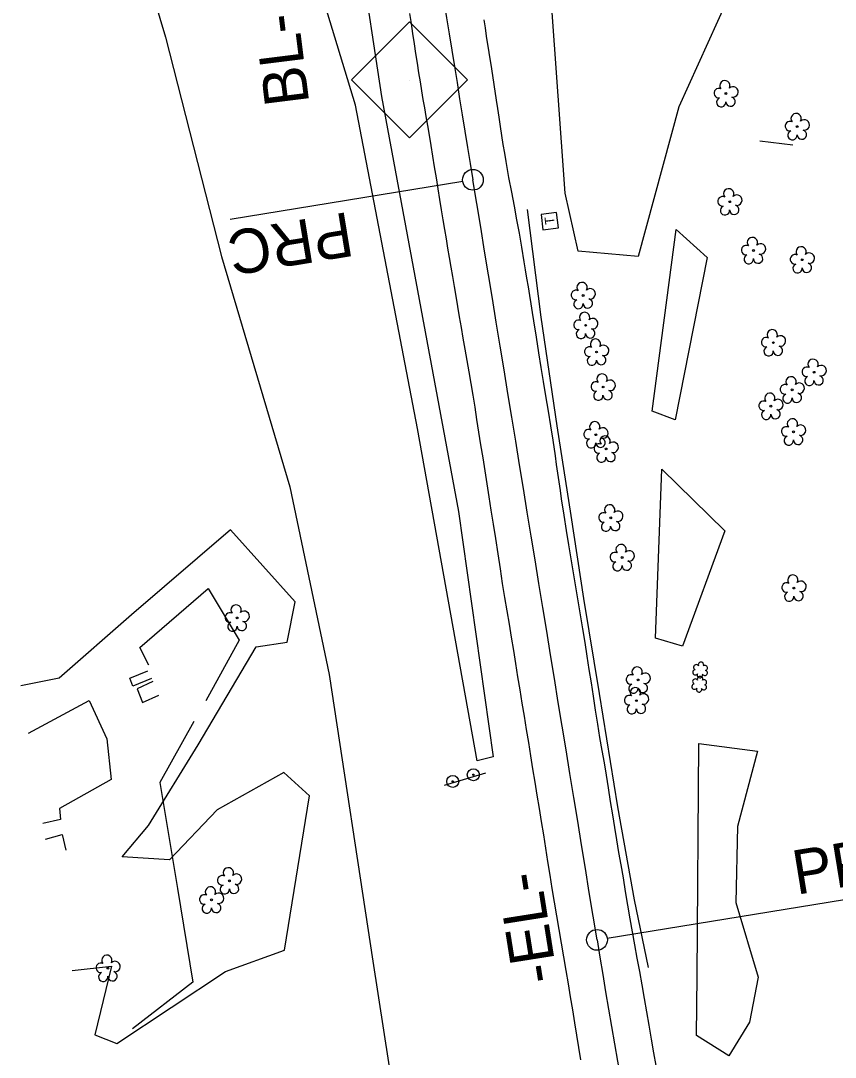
# Model space of a CAD drawing. Extents: x 477009 to 479892, y 492858 to 496862.
# Drawn here: x 478207.5 to 478502.1, y 495186.3 to 495561.1 of the extents above; entities that cross this region are included whole.
import ezdxf

# ---------------------------------------------------------------- set-up
doc = ezdxf.new("R2010")
doc.units = 0
for name, color, linetype in [('CTL Secondary Horizontal and Vertical CELL', 7, 'Continuous'), ('CTL Secondary Horizontal and Vertical Text', 7, 'Continuous'), ('Exist Guardrail', 7, 'Continuous'), ('Exist Horizontal Alignment', 7, 'Continuous'), ('Exist Horizontal Alignment Direction Label', 7, 'Continuous'), ('Exist Other Culture Area Outline', 7, 'Continuous'), ('Exist Other Culture Fence Line', 7, 'Continuous'), ('Exist Other Culture Sign', 7, 'Continuous'), ('Exist Other Culture Sign Post CELL', 7, 'Continuous'), ('Exist Roads EOP', 7, 'Continuous'), ('Exist Roads Soil', 7, 'Continuous'), ('Exist Structure Minor Footbridge', 7, 'Continuous'), ('Exist Utilities Telephone Pedestal CELL', 7, 'Continuous'), ('Exist Vegetation Shrub CELL', 7, 'Continuous'), ('Exist Vegetation Tree CELL', 7, 'Continuous'), ('Exist Vegetation Woods Line', 7, 'Continuous')]:
    doc.layers.add(name, color=color, linetype=linetype)

msp = doc.modelspace()

# ---------------------------------------------------------------- linework, layer by layer
at = {"layer": 'CTL Secondary Horizontal and Vertical CELL'}
msp.add_line((478348.02, 495539.64), (478348.02, 495539.64), dxfattribs=at)
msp.add_lwpolyline([(478327.16, 495539.71), (478348.13, 495560.67), (478369.13, 495539.67), (478348.16, 495518.71)], close=True, dxfattribs=at)
at = {"layer": 'Exist Guardrail'}
msp.add_lwpolyline([(478390.72, 495492.81), (478395.61, 495453.92), (478401.39, 495414.56), (478406.41, 495382.15), (478411, 495352.2), (478416.72, 495317.79), (478423.3, 495276.84), (478429.41, 495243.13), (478434.41, 495218.68)], dxfattribs=at)
at = {"layer": 'Exist Horizontal Alignment'}
for p, q in [((478367.35, 495502.96), (478283.24, 495489.18)), ((478419.63, 495229.31), (478538.1, 495248.58))]:
    msp.add_line(p, q, dxfattribs=at)
for centre in [(478371.05, 495503.57), (478415.93, 495228.7)]:
    msp.add_circle(centre, 3.75, dxfattribs=at)
for centre, radius, start, end in [((501490.44, 499291.54), 23427.66, 188.840055, 189.304896), ((233727.31, 455420.15), 247905.71, 9.2405286, 9.3048963), ((482394.4, 495875.96), 4030.78, 189.24053, 192.1328)]:
    msp.add_arc(centre, radius, start, end, dxfattribs=at)
at = {"layer": 'Exist Other Culture Area Outline'}
for points in [[(478254.78, 495323.26), (478248.04, 495320.44), (478246.94, 495323.36), (478253.52, 495326.05)], [(478255.3, 495322.09), (478249.61, 495319.47), (478251.55, 495314.53), (478257.5, 495317.21)], [(478216.47, 495265.13), (478222.49, 495266.77), (478223.8, 495261.18)]]:
    msp.add_lwpolyline(points, dxfattribs=at)
at = {"layer": 'Exist Other Culture Fence Line'}
for points in [[(478253.89, 495327.99), (478250.6, 495334.44), (478275.37, 495355.8), (478286.52, 495337.09), (478274.45, 495315.11)], [(478270.07, 495307.7), (478257.89, 495285.57), (478264.17, 495247.34), (478269.8, 495213.45), (478247.95, 495196.55)]]:
    msp.add_lwpolyline(points, dxfattribs=at)
at = {"layer": 'Exist Other Culture Sign'}
msp.add_line((478375.65, 495289.05), (478360.61, 495284.48), dxfattribs=at)
at = {"layer": 'Exist Other Culture Sign Post CELL'}
for centre, radius in [((478371.21, 495288.41), 2.18), ((478363.75, 495286), 2.18), ((478363.75, 495286), 0.24), ((478371.21, 495288.41), 0.24)]:
    msp.add_circle(centre, radius, dxfattribs=at)
at = {"layer": 'Exist Roads EOP'}
for points in [[(478410.13, 495185.29), (478409.39, 495189.74), (478408.66, 495194.22), (478407.92, 495198.76), (478407.17, 495203.37), (478406.38, 495208.07), (478405.58, 495212.84), (478404.76, 495217.68), (478403.93, 495222.55), (478403.09, 495227.46), (478402.24, 495232.41), (478401.39, 495237.36), (478400.56, 495242.31), (478399.76, 495247.23), (478398.98, 495252.14), (478398.2, 495257.03), (478397.43, 495261.88), (478396.65, 495266.7), (478395.87, 495271.49), (478395.09, 495276.26), (478394.31, 495281.03), (478393.54, 495285.79), (478392.77, 495290.55), (478392, 495295.31), (478391.23, 495300.07), (478390.45, 495304.83), (478389.66, 495309.59), (478388.87, 495314.36), (478388.09, 495319.12), (478387.32, 495323.88), (478386.56, 495328.63), (478385.79, 495333.39), (478385.02, 495338.15), (478384.23, 495342.91), (478383.43, 495347.68), (478382.62, 495352.55), (478381.8, 495357.62), (478380.97, 495362.88), (478380.14, 495368.34), (478379.31, 495373.8), (478378.5, 495379.04), (478377.71, 495384.08), (478376.94, 495388.9), (478376.19, 495393.61), (478375.44, 495398.32), (478374.7, 495403.02), (478373.97, 495407.71), (478373.25, 495412.35), (478372.53, 495416.88), (478371.82, 495421.32), (478371.12, 495425.66), (478370.41, 495429.91), (478369.7, 495434.1), (478368.99, 495438.22), (478368.28, 495442.28), (478367.57, 495446.27), (478366.89, 495450.18), (478366.22, 495454.01), (478365.58, 495457.76), (478364.96, 495461.44), (478364.35, 495465.04), (478363.75, 495468.57), (478363.16, 495472.01), (478362.59, 495475.42), (478362.01, 495478.82), (478361.45, 495482.22), (478360.89, 495485.6), (478360.32, 495489.06), (478359.73, 495492.67), (478359.12, 495496.42), (478358.48, 495500.33), (478357.83, 495504.29), (478357.19, 495508.21), (478356.55, 495512.1), (478355.92, 495515.95), (478355.3, 495519.68), (478354.72, 495523.19), (478354.16, 495526.49), (478353.63, 495529.57), (478353.12, 495532.59), (478352.6, 495535.72), (478352.08, 495538.95), (478351.55, 495542.29), (478351.01, 495545.72), (478350.46, 495549.22), (478349.91, 495552.8), (478349.36, 495556.44), (478348.79, 495560.12), (478348.22, 495563.76)], [(478374.95, 495561.47), (478375.43, 495558.51), (478375.9, 495555.53), (478376.83, 495549.61), (478377.73, 495543.76), (478378.62, 495538.04), (478379.51, 495532.37), (478379.97, 495529.37), (478380.44, 495526.21), (478380.93, 495522.9), (478381.43, 495519.57), (478381.93, 495516.35), (478382.43, 495513.22), (478382.94, 495510.2), (478383.94, 495504.46), (478384.95, 495499.1), (478385.93, 495494.02), (478386.85, 495489.12), (478387.74, 495484.25), (478388.61, 495479.25), (478389.52, 495473.91), (478389.99, 495471.02), (478390.49, 495467.98), (478390.99, 495464.87), (478391.48, 495461.77), (478391.98, 495458.67), (478392.47, 495455.57), (478392.95, 495452.52), (478393.89, 495446.63), (478394.8, 495441.04), (478395.66, 495435.75), (478396.48, 495430.69), (478397.34, 495425.39), (478398.25, 495419.87), (478399.1, 495414.57), (478399.9, 495409.43), (478400.75, 495403.73), (478401.2, 495400.63), (478401.65, 495397.47), (478402.11, 495394.33), (478402.56, 495391.23), (478403.01, 495388.17), (478403.9, 495382.27), (478404.77, 495376.78), (478405.62, 495371.55), (478406.45, 495366.45), (478407.3, 495361.4), (478408.17, 495356.33), (478409.03, 495351.27), (478409.87, 495346.24), (478410.69, 495341.22), (478411.5, 495336.21), (478412.29, 495331.27), (478413.03, 495326.49), (478413.76, 495321.71), (478414.51, 495316.78), (478415.29, 495311.77), (478416.09, 495306.75), (478416.89, 495301.87), (478417.69, 495297.24), (478418.47, 495292.74), (478419.22, 495288.27), (478419.97, 495283.66), (478420.74, 495278.77), (478421.51, 495273.89), (478422.26, 495269.29), (478423, 495264.83), (478423.76, 495260.35), (478424.54, 495255.8), (478425.34, 495251.09), (478426.16, 495246.24), (478427, 495241.23), (478427.84, 495236.26), (478428.68, 495231.56), (478429.52, 495226.91), (478430.39, 495222.13), (478431.27, 495217.27), (478432.15, 495212.4), (478433.01, 495207.54), (478433.85, 495202.72), (478434.69, 495197.84), (478435.55, 495192.81), (478436.39, 495187.86), (478437.19, 495183.22)]]:
    msp.add_lwpolyline(points, dxfattribs=at)
at = {"layer": 'Exist Roads Soil'}
msp.add_lwpolyline([(478210.3, 495303.44), (478232.25, 495315.31), (478238.65, 495301.38), (478240.29, 495286.71), (478221.56, 495276.27), (478221.89, 495272.23), (478215.56, 495270.82)], dxfattribs=at)
at = {"layer": 'Exist Structure Minor Footbridge'}
msp.add_line((478486.71, 495516.11), (478474.86, 495517.49), dxfattribs=at)
at = {"layer": 'Exist Utilities Telephone Pedestal CELL'}
msp.add_line((478398.81, 495488.52), (478398.81, 495488.52), dxfattribs=at)
msp.add_lwpolyline([(478401.95, 495486.16), (478401.27, 495491.71), (478395.72, 495491.04), (478396.39, 495485.49), (478401.95, 495486.16)], dxfattribs=at)
at = {"layer": 'Exist Vegetation Shrub CELL'}
for p, q in [((478453.29, 495326.16), (478453.29, 495326.16)), ((478452.96, 495320.98), (478452.96, 495320.98))]:
    msp.add_line(p, q, dxfattribs=at)
for centre, radius, start, end in [((478451.81, 495327.29), 0.968, 35.8908, 245.4216), ((478453.52, 495328.2), 0.99, 334.8391, 200.4717), ((478454.97, 495327.03), 0.929, 284.4567, 126.0861), ((478451.49, 495325.45), 0.955, 95.1099, 327.9534), ((478453.17, 495324.47), 0.984, 151.2797, 21.387), ((478453.19, 495323.02), 0.99, 334.8391, 200.4717), ((478454.93, 495325.23), 0.937, 204.9913, 73.4601), ((478451.16, 495320.27), 0.955, 95.1099, 327.9534), ((478451.48, 495322.11), 0.968, 35.8908, 245.4216), ((478452.84, 495319.29), 0.984, 151.2797, 21.387), ((478454.6, 495320.05), 0.937, 204.9913, 73.4601), ((478454.64, 495321.85), 0.929, 284.4567, 126.0861)]:
    msp.add_arc(centre, radius, start, end, dxfattribs=at)
at = {"layer": 'Exist Vegetation Tree CELL'}
for p, q in [((478462.55, 495534.76), (478462.55, 495534.76)), ((478488.32, 495522.82), (478488.32, 495522.82)), ((478463.92, 495495.63), (478463.92, 495495.63)), ((478472.5, 495477.99), (478472.5, 495477.99)), ((478490.15, 495474.66), (478490.15, 495474.66)), ((478410.91, 495461.75), (478410.91, 495461.75)), ((478411.82, 495450.95), (478411.82, 495450.95)), ((478479.7, 495444.68), (478479.7, 495444.68)), ((478415.77, 495441.29), (478415.77, 495441.29)), ((478494.42, 495433.98), (478494.42, 495433.98)), ((478418.12, 495428.64), (478418.12, 495428.64)), ((478486.49, 495427.63), (478486.49, 495427.63)), ((478478.81, 495421.72), (478478.81, 495421.72)), ((478415.52, 495411.39), (478415.52, 495411.39)), ((478486.98, 495412.43), (478486.98, 495412.43)), ((478419.2, 495406.25), (478419.2, 495406.25)), ((478420.88, 495381.31), (478420.88, 495381.31)), ((478425.01, 495366.98), (478425.01, 495366.98)), ((478487.14, 495355.94), (478487.14, 495355.94)), ((478285.77, 495345.12), (478285.77, 495345.12)), ((478430.8, 495322.71), (478430.8, 495322.71)), ((478430.18, 495315.22), (478430.18, 495315.22)), ((478283, 495250.08), (478283, 495250.08)), ((478276.52, 495243.17), (478276.52, 495243.17)), ((478239.06, 495218.47), (478239.06, 495218.47))]:
    msp.add_line(p, q, dxfattribs=at)
for centre in [(478462.55, 495534.76), (478488.32, 495522.82), (478463.92, 495495.63), (478472.5, 495477.99), (478490.15, 495474.66), (478410.91, 495461.75), (478411.82, 495450.95), (478479.7, 495444.68), (478415.77, 495441.29), (478494.42, 495433.98), (478418.12, 495428.64), (478486.49, 495427.63), (478478.81, 495421.72), (478415.52, 495411.39), (478486.98, 495412.43), (478419.2, 495406.25), (478420.88, 495381.31), (478425.01, 495366.98), (478487.14, 495355.94), (478285.77, 495345.12), (478430.8, 495322.71), (478430.18, 495315.22), (478283, 495250.08), (478276.52, 495243.17), (478239.06, 495218.47)]:
    msp.add_circle(centre, 0.326, dxfattribs=at)
for centre, radius, start, end in [((478462.17, 495537.63), 1.86, 330.1651, 219.7134), ((478465.1, 495535.35), 1.9, 257.1011, 134.1999), ((478459.95, 495534.91), 1.73, 62.6636, 279.3457), ((478464.22, 495531.86), 1.7, 181.2822, 74.56), ((478460.85, 495531.64), 1.69, 111.5671, 6.231), ((478487.93, 495525.7), 1.86, 330.1651, 219.7134), ((478485.71, 495522.98), 1.73, 62.6636, 279.3457), ((478490.87, 495523.41), 1.9, 257.1011, 134.1999), ((478486.61, 495519.7), 1.69, 111.5671, 6.231), ((478489.99, 495519.92), 1.7, 181.2822, 74.56), ((478463.54, 495498.51), 1.86, 330.1651, 219.7134), ((478461.32, 495495.79), 1.73, 62.6636, 279.3457), ((478466.47, 495496.22), 1.9, 257.1011, 134.1999), ((478462.22, 495492.51), 1.69, 111.5671, 6.231), ((478465.6, 495492.73), 1.7, 181.2822, 74.56), ((478472.11, 495480.86), 1.86, 330.1651, 219.7134), ((478469.89, 495478.14), 1.73, 62.6636, 279.3457), ((478475.05, 495478.57), 1.9, 257.1011, 134.1999), ((478489.77, 495477.53), 1.86, 330.1651, 219.7134), ((478492.7, 495475.25), 1.9, 257.1011, 134.1999), ((478470.79, 495474.87), 1.69, 111.5671, 6.231), ((478474.17, 495475.09), 1.7, 181.2822, 74.56), ((478487.55, 495474.81), 1.73, 62.6636, 279.3457), ((478491.82, 495471.76), 1.7, 181.2822, 74.56), ((478488.45, 495471.54), 1.69, 111.5671, 6.231), ((478410.53, 495464.62), 1.86, 330.1651, 219.7134), ((478408.31, 495461.9), 1.73, 62.6636, 279.3457), ((478413.46, 495462.34), 1.9, 257.1011, 134.1999), ((478409.21, 495458.63), 1.69, 111.5671, 6.231), ((478412.58, 495458.85), 1.7, 181.2822, 74.56), ((478411.44, 495453.82), 1.86, 330.1651, 219.7134), ((478409.22, 495451.1), 1.73, 62.6636, 279.3457), ((478414.37, 495451.54), 1.9, 257.1011, 134.1999), ((478410.12, 495447.83), 1.69, 111.5671, 6.231), ((478413.5, 495448.05), 1.7, 181.2822, 74.56), ((478479.31, 495447.55), 1.86, 330.1651, 219.7134), ((478482.25, 495445.27), 1.9, 257.1011, 134.1999), ((478415.39, 495444.16), 1.86, 330.1651, 219.7134), ((478418.32, 495441.87), 1.9, 257.1011, 134.1999), ((478477.09, 495444.83), 1.73, 62.6636, 279.3457), ((478481.37, 495441.78), 1.7, 181.2822, 74.56), ((478413.16, 495441.44), 1.73, 62.6636, 279.3457), ((478414.07, 495438.16), 1.69, 111.5671, 6.231), ((478417.44, 495438.39), 1.7, 181.2822, 74.56), ((478477.99, 495441.56), 1.69, 111.5671, 6.231), ((478491.82, 495434.13), 1.73, 62.6636, 279.3457), ((478494.04, 495436.85), 1.86, 330.1651, 219.7134), ((478496.97, 495434.57), 1.9, 257.1011, 134.1999), ((478417.73, 495431.51), 1.86, 330.1651, 219.7134), ((478486.11, 495430.5), 1.86, 330.1651, 219.7134), ((478492.72, 495430.86), 1.69, 111.5671, 6.231), ((478496.09, 495431.08), 1.7, 181.2822, 74.56), ((478415.51, 495428.79), 1.73, 62.6636, 279.3457), ((478420.67, 495429.23), 1.9, 257.1011, 134.1999), ((478483.89, 495427.78), 1.73, 62.6636, 279.3457), ((478489.04, 495428.22), 1.9, 257.1011, 134.1999), ((478416.41, 495425.52), 1.69, 111.5671, 6.231), ((478419.79, 495425.74), 1.7, 181.2822, 74.56), ((478478.42, 495424.59), 1.86, 330.1651, 219.7134), ((478484.79, 495424.51), 1.69, 111.5671, 6.231), ((478488.16, 495424.73), 1.7, 181.2822, 74.56), ((478476.2, 495421.87), 1.73, 62.6636, 279.3457), ((478481.35, 495422.31), 1.9, 257.1011, 134.1999), ((478477.1, 495418.6), 1.69, 111.5671, 6.231), ((478480.48, 495418.82), 1.7, 181.2822, 74.56), ((478486.59, 495415.3), 1.86, 330.1651, 219.7134), ((478415.13, 495414.27), 1.86, 330.1651, 219.7134), ((478418.07, 495411.98), 1.9, 257.1011, 134.1999), ((478484.37, 495412.58), 1.73, 62.6636, 279.3457), ((478489.53, 495413.02), 1.9, 257.1011, 134.1999), ((478412.91, 495411.55), 1.73, 62.6636, 279.3457), ((478413.81, 495408.27), 1.69, 111.5671, 6.231), ((478417.19, 495408.49), 1.7, 181.2822, 74.56), ((478418.81, 495409.12), 1.86, 330.1651, 219.7134), ((478485.27, 495409.31), 1.69, 111.5671, 6.231), ((478488.65, 495409.53), 1.7, 181.2822, 74.56), ((478416.59, 495406.4), 1.73, 62.6636, 279.3457), ((478421.75, 495406.83), 1.9, 257.1011, 134.1999), ((478417.5, 495403.12), 1.69, 111.5671, 6.231), ((478420.87, 495403.35), 1.7, 181.2822, 74.56), ((478420.5, 495384.18), 1.86, 330.1651, 219.7134), ((478423.43, 495381.9), 1.9, 257.1011, 134.1999), ((478418.28, 495381.46), 1.73, 62.6636, 279.3457), ((478419.18, 495378.19), 1.69, 111.5671, 6.231), ((478422.55, 495378.41), 1.7, 181.2822, 74.56), ((478422.4, 495367.13), 1.73, 62.6636, 279.3457), ((478424.63, 495369.85), 1.86, 330.1651, 219.7134), ((478427.56, 495367.56), 1.9, 257.1011, 134.1999), ((478423.31, 495363.85), 1.69, 111.5671, 6.231), ((478426.68, 495364.08), 1.7, 181.2822, 74.56), ((478484.53, 495356.1), 1.73, 62.6636, 279.3457), ((478486.75, 495358.82), 1.86, 330.1651, 219.7134), ((478489.69, 495356.53), 1.9, 257.1011, 134.1999), ((478485.44, 495352.82), 1.69, 111.5671, 6.231), ((478488.81, 495353.05), 1.7, 181.2822, 74.56), ((478285.39, 495347.99), 1.86, 330.1651, 219.7134), ((478283.17, 495345.27), 1.73, 62.6636, 279.3457), ((478288.32, 495345.71), 1.9, 257.1011, 134.1999), ((478284.07, 495342), 1.69, 111.5671, 6.231), ((478287.45, 495342.22), 1.7, 181.2822, 74.56), ((478430.42, 495325.58), 1.86, 330.1651, 219.7134), ((478428.2, 495322.86), 1.73, 62.6636, 279.3457), ((478433.35, 495323.3), 1.9, 257.1011, 134.1999), ((478429.1, 495319.59), 1.69, 111.5671, 6.231), ((478429.79, 495318.09), 1.86, 330.1651, 219.7134), ((478432.47, 495319.81), 1.7, 181.2822, 74.56), ((478427.57, 495315.37), 1.73, 62.6636, 279.3457), ((478432.73, 495315.81), 1.9, 257.1011, 134.1999), ((478428.47, 495312.1), 1.69, 111.5671, 6.231), ((478431.85, 495312.32), 1.7, 181.2822, 74.56), ((478282.62, 495252.95), 1.86, 330.1651, 219.7134), ((478285.55, 495250.67), 1.9, 257.1011, 134.1999), ((478280.4, 495250.23), 1.73, 62.6636, 279.3457), ((478281.3, 495246.96), 1.69, 111.5671, 6.231), ((478284.67, 495247.18), 1.7, 181.2822, 74.56), ((478273.91, 495243.32), 1.73, 62.6636, 279.3457), ((478276.13, 495246.04), 1.86, 330.1651, 219.7134), ((478279.07, 495243.76), 1.9, 257.1011, 134.1999), ((478274.81, 495240.05), 1.69, 111.5671, 6.231), ((478278.19, 495240.27), 1.7, 181.2822, 74.56), ((478238.68, 495221.35), 1.86, 330.1651, 219.7134), ((478236.46, 495218.63), 1.73, 62.6636, 279.3457), ((478241.61, 495219.06), 1.9, 257.1011, 134.1999), ((478237.36, 495215.35), 1.69, 111.5671, 6.231), ((478240.74, 495215.57), 1.7, 181.2822, 74.56)]:
    msp.add_arc(centre, radius, start, end, dxfattribs=at)
at = {"layer": 'Exist Vegetation Woods Line'}
for points in [[(478411.07, 495654.8), (478425.25, 495605.78), (478454.36, 495592.76), (478468.93, 495594.49), (478462.96, 495568.52), (478445.54, 495529.93), (478430.84, 495475.89), (478409.15, 495477.74), (478404.41, 495498.69), (478398, 495587.65), (478389.57, 495642.98)], [(478322.37, 495637.01), (478338.02, 495533.69), (478365.85, 495383.63), (478378.39, 495294.94), (478372.6, 495293.46), (478351, 495413.63), (478328.59, 495530.52), (478316.59, 495570.4), (478310.42, 495599.68), (478303.14, 495633.48)], [(478243.88, 495609.04), (478259.87, 495555.11), (478280.1, 495475.88), (478304.88, 495392.52), (478319.11, 495324.69), (478334.86, 495221.02), (478346.46, 495146.16), (478323.55, 495132.51), (478332.16, 495119.51)], [(478455.78, 495475.51), (478444.23, 495416.82), (478435.82, 495419.96), (478444.55, 495485.54), (478455.78, 495475.51)], [(478439.34, 495398.98), (478462.14, 495376.63), (478446.86, 495334.91), (478437.1, 495337.79), (478439.34, 495398.98)], [(478226.12, 495217.59), (478240.4, 495219.15), (478234.28, 495194.36), (478242.24, 495191.22), (478281.58, 495217.23), (478302.91, 495224.93), (478311.98, 495280.77), (478302.63, 495289.21), (478278.51, 495275.73), (478261.35, 495257.59), (478244.17, 495258.72), (478253.78, 495270.01), (478271.67, 495299.24), (478292.7, 495334.73), (478303.94, 495336.35), (478306.77, 495351), (478283.37, 495376.99), (478247.59, 495346.25), (478221.45, 495323.39), (478207.53, 495320.61)], [(478452.72, 495299.73), (478473.95, 495296.98), (478466.68, 495269.67), (478466.18, 495242.22), (478474.22, 495215.18), (478471.07, 495198.94), (478463.66, 495186.72), (478451.95, 495194.14), (478452.11, 495215.6), (478452.72, 495299.73)]]:
    msp.add_lwpolyline(points, dxfattribs=at)

# ---------------------------------------------------------------- texts
at = {"layer": 'CTL Secondary Horizontal and Vertical Text'}
msp.add_text('BL-108', height=16, rotation=97.1248, dxfattribs=at).set_placement((478311.9, 495531.34))
at = {"layer": 'Exist Horizontal Alignment'}
for rotation, p in [(189.3049, (478326.09, 495492)), (9.2405, (478488.09, 495244.99))]:
    msp.add_text('PRC', height=16, rotation=rotation, dxfattribs=at).set_placement(p)
at = {"layer": 'Exist Horizontal Alignment Direction Label'}
msp.add_text('-EL-', height=16, rotation=99.0069, dxfattribs=at).set_placement((478401.75, 495214.13))
at = {"layer": 'Exist Utilities Telephone Pedestal CELL'}
msp.add_text('T', height=3.42, rotation=96.889, dxfattribs=at).set_placement((478400.65, 495487.6))

doc.saveas('drawing.dxf')
